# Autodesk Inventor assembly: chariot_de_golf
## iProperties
Created: 2011-01
Part Number: chariot_de_golf
Document SubType Name: Assembly
Designer: eric
Norme de conversion: STEP AP214IS
Nom du fichier: chariot_de_golf.STEP
Préprocesseur: SolidWorks 2007
Postprocesseur: Build: 342, Release: 2008 SP3 - Date: Tue 05/27/2008
Unités envoyées: MILLIMETERS
Incertitude: 1e-05
Author: eric
